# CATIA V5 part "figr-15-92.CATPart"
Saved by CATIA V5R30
Part number: Part1
Bounding box of the stored display mesh (mm): x -40 to 40, y -60 to 60, z 0 to 2
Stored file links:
  D:\PROJECTS\CATIA V56R 2020\Resources\Parts File\c15_catia_v5_6r2020_prt\figr-15-92.CATPart
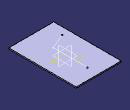
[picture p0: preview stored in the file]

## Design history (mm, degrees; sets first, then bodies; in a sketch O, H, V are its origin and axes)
SheetMetalParameters1: Thickness 2, BendRadius 4, KFactor 0.400515 {= log(min(100,max(20*SheetMetalParameters1.BendRadius,SheetMetalParameters1.Thickness)/SheetMetalParameters1.Thickness))/log(100)/2}, ReliefRadialLength 1, ReliefAxialLength 2, MinimumBendRadius 0
Body1 (main body)
  Sketch1 on xy-plane, origin (0, 0, 0), H (-1, 0, 0), V (0, -1, 0)
    line L1 (40, 60) -> (40, -60)
    line L2 (40, -60) -> (-40, -60)
    line L3 (-40, -60) -> (-40, 60)
    line L4 (-40, 60) -> (40, 60)
    length L4 = 80
    length L1 = 120
    vertical: L1 V, L3 V
    horizontal: L2 H, L4 H
    equidistance: L1 L3 O, L2 L4 O
  Wall1: Thickness 2, Profile Sketch1, OffsetValue 0
  Sketch2 on face of Wall1, origin (0, 0, 2), H (1, 0, 0), V (0, 1, 0)
    line L1 (0, 40.0798) -> (0, -21.0085)
    line L2 (0, -21.0085) -> (-27, -32)
    vertical: L1 V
